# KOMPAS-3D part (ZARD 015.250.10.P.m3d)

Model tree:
1. Плоскость XY
2. Плоскость ZX
3. Плоскость ZY
4. Ось X
5. Ось Y
6. Ось Z
7. Начало координат
8. Смещенная плоскость:1
     Расстояние = 100
9. Смещенная плоскость:2
     Расстояние = 100
10. Булева операция:1
11. Булева операция:2
